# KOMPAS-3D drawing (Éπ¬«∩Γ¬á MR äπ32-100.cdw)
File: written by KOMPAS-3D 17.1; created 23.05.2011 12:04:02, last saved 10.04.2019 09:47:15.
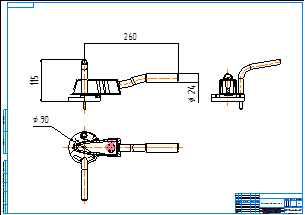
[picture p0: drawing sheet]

Sheet 1: A1, landscape

Title block, sheet 1: name: Рукоятка MR Ду32-100; material: Внимание! Данный продукт является объектом авторского права ООО «Торговый Дом АДЛ». / Запрещается изменение, копирование, распространение / (в том числе путем копирования на другие сайты и ресурсы в Интернете) / или любое иное использование информации и объектов без предварительного / согласия правообладателя (ООО «Торговый Дом АДЛ»).; scale: 1:1; sheets: 1; organisation: ООО "Торговый дом АДЛ"; sheet format: A1; stored path: \\adlc.lan\data\АДЛ_ПКД\3D-модели\ADL production\Дисковые поворотные затворы ГРАНВЭЛ\Рукоятки ГРАНВЭЛ\тип MR\KOMPAS 2D\Рукоятка MR Ду32-100.cdw

Views: Спереди 1, Проекционный вид 2, Проекционный вид 3
Dimensions and other numbers on the sheet: 115; 90; 260; 24; 1:1; 1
